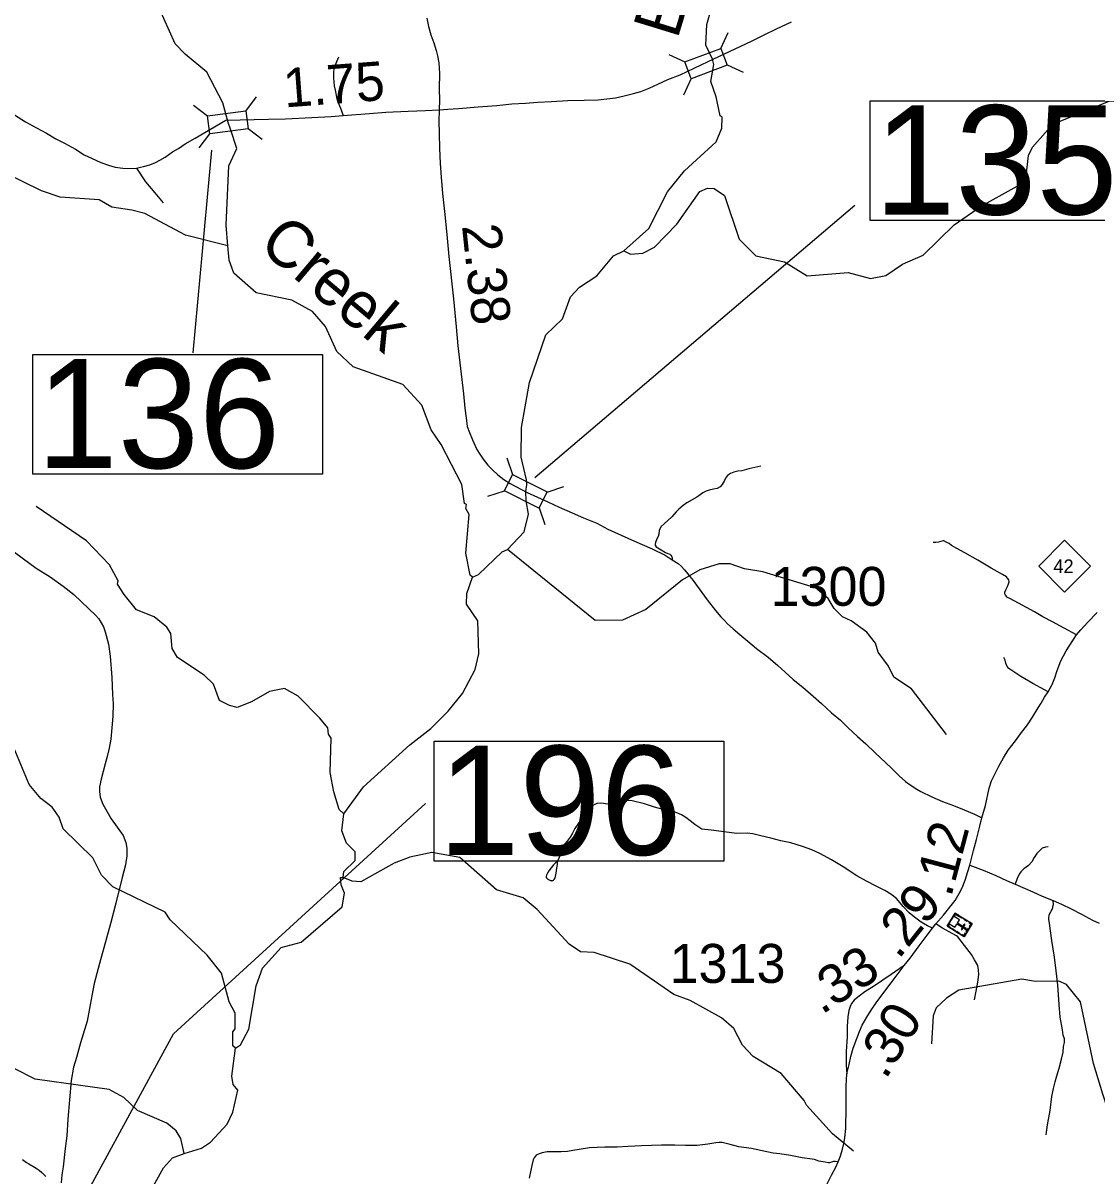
# Model space of a CAD drawing. Extents: x 2290615 to 2522933, y 819489 to 1012715.
# Drawn here: x 2331750 to 2345527, y 928394 to 943186 of the extents above; entities that cross this region are included whole.
import ezdxf

# ---------------------------------------------------------------- set-up
doc = ezdxf.new("R2010")
doc.units = 0
for name, color, linetype in [('Exist Cultural Church with Cemetery CELL', 7, 'Continuous'), ('Exist Hydrographic Creek Single Shore', 7, 'Continuous'), ('Exist Hydrographic Creek Single Shore Label', 7, 'Continuous'), ('Exist Hydrographic Misc Water Feature', 7, 'Continuous'), ('Exist Road Non-System Type 51', 7, 'Continuous'), ('Exist Road Primary NC Attributed', 7, 'Continuous'), ('Exist Road Primary NC Mileage Hundredths English Label', 7, 'Continuous'), ('Exist Road Primary NC Shield CELL', 7, 'Continuous'), ('Exist Road Primary NC Shield Number Label', 7, 'Continuous'), ('Exist Road Secondary Mileage Hundredths English Label', 7, 'Continuous'), ('Exist Road Secondary Structure Standard Bridge CELL', 7, 'Continuous'), ('Exist Road Secondary Structure Standard Bridge Number Label', 7, 'Continuous'), ('Exist Road Secondary Type 41 Attributed', 7, 'Continuous'), ('Exist Road Secondary Type 51 Attributed', 7, 'Continuous'), ('Exist Road Secondary Type 51 Number Label', 7, 'Continuous')]:
    doc.layers.add(name, color=color, linetype=linetype)

msp = doc.modelspace()

# ---------------------------------------------------------------- linework, layer by layer
at = {"layer": 'Exist Cultural Church with Cemetery CELL'}
for points in [[(2343927, 931632), (2343822, 931462), (2343606, 931597), (2343710, 931766)], [(2343693, 931738), (2343703, 931732), (2343714, 931750), (2343749, 931729), (2343755, 931739), (2343710, 931766)], [(2343623, 931625), (2343633, 931619), (2343621, 931600), (2343655, 931579), (2343650, 931569), (2343606, 931597)], [(2343688, 931729), (2343629, 931634), (2343706, 931586), (2343732, 931629), (2343802, 931586), (2343784, 931558), (2343794, 931553), (2343811, 931581), (2343847, 931558), (2343853, 931568), (2343817, 931590), (2343835, 931619), (2343825, 931624), (2343808, 931596), (2343738, 931639), (2343765, 931682)], [(2343770, 931729), (2343807, 931706), (2343801, 931697), (2343764, 931719)], [(2343827, 931694), (2343864, 931671), (2343858, 931661), (2343821, 931684)], [(2343890, 931655), (2343884, 931645), (2343911, 931628), (2343890, 931593), (2343899, 931588), (2343927, 931632)], [(2343673, 931568), (2343710, 931545), (2343704, 931536), (2343667, 931559)], [(2343729, 931533), (2343766, 931511), (2343760, 931501), (2343723, 931524)], [(2343785, 931485), (2343791, 931495), (2343818, 931478), (2343840, 931512), (2343849, 931507), (2343822, 931462)], [(2343888, 931569), (2343860, 931525), (2343851, 931531), (2343878, 931575)]]:
    msp.add_lwpolyline(points, close=True, dxfattribs=at)
at = {"layer": 'Exist Hydrographic Creek Single Shore'}
for points in [[(2339458, 940266), (2339780, 940551), (2340016, 941021), (2340237, 941289), (2340641, 941663), (2340714, 941837), (2340721, 941979), (2340695, 941997), (2340643, 942238), (2340573, 942435), (2340610, 942656), (2340595, 942721), (2340510, 942902), (2340523, 943169), (2340787, 944105), (2340842, 944357), (2340819, 944904), (2340792, 945031), (2340750, 945105), (2340758, 945138), (2340732, 945163), (2340653, 945554), (2340650, 945787)], [(2334376, 940329), (2334356, 940594), (2334388, 941354), (2334494, 941578), (2334412, 941823), (2334381, 941910), (2334312, 942162), (2334107, 942557), (2333830, 942788), (2333703, 942921), (2333481, 943408)], [(2337517, 936076), (2337484, 936101), (2337431, 936385), (2337475, 936882), (2337432, 936959), (2337440, 937009), (2337415, 937024), (2337378, 937265), (2337114, 937780), (2336987, 937968), (2336866, 938285), (2336621, 938547), (2335986, 938774), (2335775, 938972), (2335629, 939294), (2335461, 939484), (2335200, 939631), (2334741, 939724), (2334455, 939978), (2334394, 940146), (2334376, 940329)], [(2337963, 936433), (2338177, 936658), (2338233, 936884), (2338203, 937058), (2338200, 937174), (2338211, 937260), (2338208, 937324), (2338140, 937615), (2338144, 937999), (2338246, 938575), (2338455, 939187), (2338669, 939390), (2338774, 939673), (2338889, 939799), (2339112, 939943), (2339326, 940198), (2339458, 940266)], [(2337517, 936076), (2337592, 936109), (2337897, 936404), (2337963, 936433)], [(2335863, 933041), (2336117, 933386), (2336710, 933926), (2336983, 934137), (2337205, 934357), (2337386, 934584), (2337548, 934893), (2337596, 935095), (2337583, 935518), (2337438, 935732), (2337445, 935867), (2337517, 936076)], [(2335856, 932223), (2335863, 932299), (2336012, 932443), (2336010, 932551), (2335901, 932665), (2335840, 932823), (2335863, 933041)], [(2334475, 930033), (2334540, 930075), (2334646, 930276), (2334740, 930835), (2334820, 931062), (2335059, 931324), (2335316, 931394), (2335844, 931849), (2335875, 932024), (2335832, 932131), (2335823, 932222), (2335856, 932223)], [(2333816, 928683), (2334040, 928752), (2334156, 928828), (2334370, 929057), (2334443, 929214), (2334506, 929493), (2334447, 929566), (2334429, 929673), (2334475, 930033)], [(2332562, 927644), (2332603, 927701), (2332669, 927720), (2332828, 927687), (2333044, 927732), (2333250, 927951), (2333551, 928498), (2333667, 928625), (2333816, 928683)]]:
    msp.add_lwpolyline(points, dxfattribs=at)
at = {"layer": 'Exist Hydrographic Misc Water Feature'}
for points in [[(2339458, 940266), (2339542, 940223), (2339700, 940233), (2339849, 940311), (2340137, 940605), (2340432, 941025), (2340532, 941068), (2340615, 941062), (2340749, 940972), (2340939, 940415), (2341150, 940201), (2341518, 940124), (2341811, 939942), (2342336, 939984), (2342620, 939910), (2342820, 939948), (2343034, 940091), (2343299, 940210), (2343695, 940597), (2344042, 940835), (2344505, 941094), (2344620, 941220), (2344650, 941487), (2344699, 941594), (2344962, 941890), (2345758, 942215)], [(2334376, 940329), (2333833, 940465), (2333313, 940742), (2333146, 940787), (2332887, 940826), (2332727, 940918), (2332227, 940953), (2331985, 941032), (2331507, 941268)], [(2335863, 933041), (2335804, 933098), (2335735, 933321), (2335690, 933572), (2335701, 934013), (2335667, 934064), (2335658, 934145), (2335557, 934269), (2335278, 934550), (2335102, 934648), (2334911, 934610), (2334679, 934476), (2334497, 934406), (2334397, 934432), (2334271, 934495), (2334193, 934702), (2334075, 934819), (2333731, 935048), (2333663, 935163), (2333644, 935356), (2333593, 935436), (2333433, 935567), (2333207, 935656), (2333046, 935856), (2332962, 935988), (2332969, 936031), (2332859, 936236), (2332563, 936542), (2331917, 936982)], [(2343598, 934058), (2343150, 934644), (2342923, 934792), (2342855, 934933), (2342719, 935115), (2342685, 935228), (2342574, 935372), (2342373, 935518), (2342264, 935566), (2342154, 935673), (2342078, 935804), (2341918, 935939), (2341240, 936147), (2341007, 936184), (2340823, 936248), (2340681, 936246), (2340432, 936170), (2340209, 936042), (2339739, 935662), (2339440, 935525), (2339090, 935521), (2337963, 936433)], [(2334475, 930033), (2334441, 930065), (2334439, 930242), (2334471, 930282), (2334469, 930483), (2334392, 930630), (2334296, 930997), (2334110, 931229), (2333638, 931679), (2333571, 931778), (2332900, 932105), (2332757, 932254), (2332646, 932476), (2332266, 932847), (2332215, 932996), (2332121, 933127), (2331978, 933236), (2331826, 933417), (2331594, 933982)], [(2342406, 928711), (2342135, 928933), (2341799, 929303), (2341773, 929361), (2341476, 929710), (2341116, 929928), (2340980, 930071), (2340869, 930286), (2340711, 930424), (2340307, 930644), (2340098, 930724), (2339535, 931111), (2339075, 931263), (2338900, 931269), (2338757, 931368), (2338344, 931814), (2338167, 931961), (2337824, 932065), (2337352, 932482), (2336993, 932546), (2336711, 932485), (2336512, 932408), (2336082, 932167), (2335973, 932176), (2335856, 932223)], [(2346076, 928291), (2346082, 928471), (2345803, 928828), (2345603, 929443), (2345483, 929839), (2345315, 930629), (2345138, 930852), (2345037, 930894), (2344737, 930888), (2344562, 930920), (2343755, 930779), (2343597, 930677), (2343466, 930550), (2343425, 930450), (2343405, 930091)], [(2333816, 928683), (2333772, 928875), (2333712, 928974), (2333595, 929071), (2333218, 929233), (2333041, 929400), (2332856, 929504), (2331905, 929635), (2331637, 929772)]]:
    msp.add_lwpolyline(points, dxfattribs=at)
at = {"layer": 'Exist Road Non-System Type 51'}
for points in [[(2335798, 942749), (2335773, 942688), (2335743, 942616), (2335734, 942563), (2335731, 942483), (2335743, 942382), (2335756, 942325), (2335776, 942214), (2335788, 942174), (2335823, 942094), (2335858, 942000)], [(2333204, 941326), (2333319, 941148), (2333439, 941007), (2333546, 940881)], [(2341216, 937500), (2341138, 937485), (2341063, 937465), (2340970, 937441), (2340918, 937435), (2340867, 937425), (2340827, 937408), (2340789, 937381), (2340762, 937348), (2340744, 937307), (2340719, 937265), (2340692, 937235), (2340656, 937213), (2340607, 937204), (2340553, 937194), (2340514, 937182), (2340473, 937159), (2340420, 937122), (2340396, 937104), (2340265, 937029), (2340217, 936996), (2340165, 936951), (2340127, 936914), (2340072, 936853), (2339974, 936761), (2339938, 936726), (2339918, 936698), (2339911, 936676), (2339908, 936630), (2339899, 936597), (2339880, 936567), (2339863, 936522), (2339858, 936500), (2339858, 936487), (2339873, 936467), (2339935, 936426), (2339993, 936395), (2340021, 936380), (2340047, 936370), (2340062, 936359), (2340071, 936347), (2340079, 936327), (2340076, 936300)], [(2345265, 935337), (2345107, 935421), (2344957, 935502), (2344834, 935567), (2344725, 935633), (2344520, 935744), (2344409, 935801), (2344381, 935818), (2344354, 935846), (2344347, 935864), (2344347, 935883), (2344358, 935914), (2344379, 935956), (2344392, 935990), (2344400, 936017), (2344396, 936041), (2344381, 936063), (2344366, 936083), (2344316, 936113), (2344172, 936191), (2343998, 936297), (2343832, 936390), (2343731, 936445), (2343663, 936485), (2343630, 936507), (2343600, 936523), (2343563, 936541), (2343563, 936541), (2343554, 936541), (2343525, 936535), (2343494, 936528), (2343461, 936523), (2343428, 936521)], [(2344901, 934607), (2344706, 934713), (2344551, 934804), (2344396, 934903), (2344375, 934932), (2344358, 934974), (2344349, 935010), (2344332, 935048)], [(2343418, 931573), (2343355, 931604), (2343272, 931652), (2343188, 931714), (2343118, 931770), (2343045, 931847), (2342954, 931953), (2342882, 932008), (2342805, 932057), (2342696, 932114), (2342569, 932177), (2342448, 932246), (2342272, 932362), (2342122, 932449), (2341970, 932532), (2341871, 932578), (2341748, 932623), (2341600, 932667), (2341472, 932693), (2341345, 932729), (2341214, 932757), (2341114, 932782), (2341038, 932791), (2340904, 932789), (2340746, 932811), (2340577, 932832), (2340460, 932845), (2340419, 932869), (2340367, 932905), (2340310, 932952), (2340252, 932993), (2340197, 933027), (2340117, 933060), (2340007, 933084), (2339852, 933124), (2339724, 933167), (2339565, 933207), (2339449, 933214), (2339399, 933203), (2339340, 933182), (2339298, 933168), (2339250, 933165), (2339198, 933175), (2339152, 933178), (2339110, 933172), (2339050, 933141), (2339019, 933114), (2338961, 933040), (2338922, 932987), (2338829, 932851), (2338797, 932794), (2338768, 932743), (2338730, 932690), (2338683, 932633), (2338668, 932614), (2338651, 932592), (2338647, 932573), (2338639, 932537), (2338634, 932516), (2338630, 932491), (2338622, 932468), (2338607, 932438)], [(2344903, 932615), (2344867, 932611), (2344823, 932598), (2344756, 932530), (2344723, 932481), (2344690, 932425), (2344648, 932378), (2344589, 932336), (2344551, 932297), (2344529, 932267), (2344504, 932209), (2344480, 932139)], [(2338607, 932438), (2338556, 932385), (2338526, 932347), (2338495, 932307), (2338478, 932279), (2338468, 932263), (2338464, 932254), (2338460, 932235), (2338462, 932222), (2338472, 932209), (2338484, 932200), (2338498, 932195), (2338515, 932187), (2338526, 932183), (2338532, 932182), (2338540, 932183), (2338546, 932185), (2338554, 932190), (2338564, 932197), (2338571, 932211), (2338581, 932236), (2338589, 932279), (2338598, 932345), (2338605, 932390), (2338608, 932417), (2338607, 932438)], [(2344876, 928920), (2344895, 929049), (2344928, 929236), (2344950, 929412), (2344968, 929518), (2344990, 929603), (2345012, 929680), (2345041, 929775), (2345074, 929893), (2345093, 929984), (2345100, 930054), (2345111, 930105), (2345111, 930153), (2345096, 930201), (2345085, 930270), (2345056, 930432), (2345041, 930593), (2345027, 930843), (2345005, 931026), (2344983, 931202), (2344950, 931415), (2344931, 931540), (2344917, 931639), (2344909, 931686), (2344909, 931708), (2344913, 931741), (2344924, 931763), (2344942, 931793), (2344953, 931811), (2344962, 931838), (2344966, 931869), (2344968, 931873), (2344964, 931930)], [(2343955, 930653), (2343976, 930764), (2343997, 930882), (2344012, 930977), (2344007, 931039), (2343997, 931093), (2343955, 931166), (2343919, 931234), (2343828, 931351), (2343742, 931462), (2343724, 931475), (2343668, 931505), (2343547, 931572), (2343461, 931628)], [(2342208, 928574), (2342168, 928579), (2342146, 928579), (2342095, 928563), (2342077, 928562), (2342040, 928571), (2341959, 928585), (2341902, 928605), (2341746, 928628), (2341594, 928658), (2341458, 928678), (2341372, 928688), (2341232, 928715), (2341095, 928745), (2340934, 928769), (2340820, 928797), (2340720, 928824), (2340682, 928824), (2340636, 928821), (2340534, 928802), (2340398, 928786), (2340250, 928784), (2340112, 928789), (2339940, 928787), (2339685, 928780), (2339513, 928773), (2339371, 928764), (2339215, 928762), (2339019, 928754), (2338883, 928732), (2338803, 928719), (2338734, 928706), (2338654, 928705), (2338568, 928704), (2338472, 928705), (2338408, 928692), (2338370, 928680), (2338334, 928661), (2338309, 928627), (2338295, 928601), (2338278, 928527), (2338265, 928467), (2338244, 928366)], [(2331742, 928604), (2331792, 928568), (2331824, 928548), (2331873, 928518), (2331916, 928492), (2331955, 928467), (2331992, 928438), (2332044, 928386)]]:
    msp.add_lwpolyline(points, dxfattribs=at)
at = {"layer": 'Exist Road Primary NC Attributed'}
for points in [[(2344049, 932987), (2344097, 933148), (2344146, 933370), (2344176, 933463), (2344269, 933651), (2344328, 933758), (2344390, 933859), (2344483, 933976), (2344548, 934067), (2344636, 934182), (2344701, 934279), (2344774, 934400), (2344811, 934459), (2344854, 934539), (2344901, 934607), (2344952, 934699), (2344985, 934786), (2345018, 934880), (2345066, 935005), (2345133, 935130), (2345178, 935206), (2345217, 935266), (2345265, 935337), (2345322, 935402), (2345410, 935501), (2345529, 935622)], [(2343898, 932383), (2343944, 932568), (2343982, 932712), (2344024, 932883), (2344049, 932987)], [(2343052, 931094), (2343129, 931188), (2343245, 931348), (2343347, 931483), (2343418, 931573), (2343461, 931628), (2343558, 931741), (2343639, 931842), (2343708, 931929), (2343759, 932018), (2343800, 932090), (2343837, 932191), (2343871, 932299), (2343898, 932383)], [(2342318, 929706), (2342349, 929825), (2342370, 929926), (2342399, 930034), (2342445, 930156), (2342480, 930247), (2342517, 930329), (2342574, 930432), (2342629, 930521), (2342694, 930617), (2342780, 930730), (2342887, 930872), (2343052, 931094)], [(2342039, 928242), (2342123, 928403), (2342177, 928508), (2342208, 928574), (2342234, 928640), (2342257, 928719), (2342280, 928811), (2342294, 928885), (2342304, 929005), (2342307, 929095), (2342311, 929187), (2342311, 929345), (2342309, 929552), (2342318, 929706)]]:
    msp.add_lwpolyline(points, dxfattribs=at)
at = {"layer": 'Exist Road Primary NC Shield CELL'}
msp.add_lwpolyline([(2344780, 936219), (2345113, 936552), (2345446, 936219), (2345113, 935886)], close=True, dxfattribs=at)
at = {"layer": 'Exist Road Secondary Structure Standard Bridge CELL'}
for p, q in [((2340704, 942861), (2340797, 943067)), ((2340033, 942782), (2340239, 942688)), ((2340783, 942649), (2340989, 942555)), ((2340226, 942265), (2340320, 942471)), ((2333937, 942132), (2334117, 941994)), ((2334609, 942058), (2334746, 942238)), ((2334638, 941834), (2334818, 941696)), ((2334010, 941585), (2334147, 941765)), ((2337958, 937607), (2338029, 937393)), ((2338472, 937169), (2338687, 937241)), ((2337711, 937114), (2337926, 937186)), ((2338371, 936967), (2338442, 936752))]:
    msp.add_line(p, q, dxfattribs=at)
for points in [[(2340239, 942688), (2340703, 942862), (2340784, 942645), (2340320, 942471)], [(2334117, 941994), (2334608, 942059), (2334639, 941830), (2334147, 941765)], [(2338029, 937393), (2338473, 937170), (2338369, 936963), (2337926, 937186)]]:
    msp.add_lwpolyline(points, close=True, dxfattribs=at)
at = {"layer": 'Exist Road Secondary Structure Standard Bridge Number Label'}
for p, q in [((2334166, 941557), (2333929, 938954)), ((2338314, 937355), (2342422, 940851))]:
    msp.add_line(p, q, dxfattribs=at)
for points in [[(2342619, 942188), (2346335, 942188), (2346335, 940651), (2342619, 940651)], [(2331874, 938934), (2335590, 938934), (2335590, 937397), (2331874, 937397)], [(2337026, 933971), (2340742, 933971), (2340742, 932435), (2337026, 932435)]]:
    msp.add_lwpolyline(points, close=True, dxfattribs=at)
msp.add_lwpolyline([(2332142, 927385), (2333681, 930217), (2336913, 933172)], dxfattribs=at)
at = {"layer": 'Exist Road Secondary Type 41 Attributed'}
msp.add_lwpolyline([(2331558, 936456), (2331919, 936194), (2332096, 936080), (2332263, 935962), (2332403, 935853), (2332684, 935587), (2332721, 935542), (2332782, 935439), (2332804, 935374), (2332847, 935219), (2332866, 935064), (2332888, 934790), (2332898, 934572), (2332907, 934452), (2332900, 934292), (2332888, 934142), (2332874, 933998), (2332854, 933881), (2332829, 933778), (2332803, 933682), (2332750, 933485), (2332730, 933386), (2332730, 933326), (2332739, 933255), (2332775, 933163), (2332824, 933073), (2332881, 932976), (2333033, 932764), (2333067, 932674), (2333081, 932601), (2333083, 932582), (2333081, 932500), (2333062, 932386), (2333021, 932223), (2332941, 931893), (2332877, 931645), (2332730, 931122), (2332664, 930863), (2332632, 930707), (2332573, 930382), (2332487, 930104), (2332434, 929916), (2332396, 929791), (2332368, 929617), (2332324, 929121), (2332313, 928909), (2332290, 928746), (2332265, 928510), (2332249, 928409), (2332237, 928306)], dxfattribs=at)
at = {"layer": 'Exist Road Secondary Type 51 Attributed'}
for points in [[(2336929, 943249), (2336950, 943143), (2336982, 943037), (2337019, 942932), (2337048, 942834), (2337067, 942766), (2337082, 942677), (2337091, 942539), (2337088, 942345), (2337092, 942199), (2337087, 942075)], [(2340538, 942694), (2341096, 942955), (2341259, 943035), (2341414, 943113), (2341607, 943201)], [(2337087, 942075), (2337199, 942080), (2337337, 942090), (2337588, 942111), (2337828, 942130), (2338022, 942148), (2338194, 942160), (2338352, 942172), (2338529, 942182), (2338741, 942191), (2338950, 942199), (2339129, 942201), (2339349, 942227), (2339463, 942252), (2339580, 942284), (2339676, 942310), (2339781, 942350), (2339894, 942402), (2340024, 942462), (2340181, 942524), (2340538, 942694)], [(2331641, 942009), (2331782, 941919), (2331921, 941841), (2332050, 941772), (2332171, 941702), (2332280, 941644), (2332422, 941567), (2332535, 941496), (2332627, 941452), (2332747, 941397), (2332848, 941363), (2332933, 941339), (2333029, 941326), (2333132, 941321), (2333204, 941326), (2333258, 941339), (2333295, 941348), (2333378, 941369), (2333448, 941397), (2333504, 941429), (2333572, 941467), (2333665, 941532), (2333745, 941579), (2333830, 941637), (2333956, 941710), (2334353, 941939)], [(2334353, 941939), (2334900, 941955), (2335118, 941958), (2335455, 941973), (2335702, 941988), (2335858, 942000), (2336193, 942028), (2336406, 942041), (2336690, 942054), (2336911, 942064), (2337087, 942075)], [(2337087, 942075), (2337085, 941929), (2337089, 941771), (2337091, 941581), (2337103, 941385), (2337116, 941207), (2337132, 940998), (2337159, 940732), (2337191, 940426), (2337214, 940193), (2337270, 939649), (2337308, 939288), (2337328, 939047), (2337363, 938753), (2337399, 938427), (2337416, 938244), (2337433, 938121), (2337449, 938008), (2337476, 937933), (2337518, 937839), (2337573, 937716), (2337608, 937654), (2337651, 937591), (2337714, 937514), (2337771, 937452), (2337839, 937391), (2337916, 937332), (2337997, 937279), (2338217, 937163)], [(2338217, 937163), (2338481, 937043), (2338626, 936975), (2338795, 936903), (2338938, 936837), (2339109, 936769), (2339251, 936694), (2339422, 936614), (2339593, 936539), (2339821, 936440), (2339988, 936359), (2340076, 936300), (2340155, 936251), (2340195, 936218), (2340235, 936169), (2340275, 936124), (2340303, 936086), (2340345, 936034), (2340390, 935974), (2340422, 935927), (2340526, 935788), (2340632, 935650), (2340701, 935570), (2340747, 935519), (2340788, 935477), (2340858, 935416), (2340947, 935341), (2341050, 935254), (2341161, 935160), (2341310, 935051), (2341432, 934945), (2341529, 934856), (2341630, 934765), (2341752, 934666), (2341887, 934550), (2341994, 934454), (2342123, 934335), (2342236, 934241), (2342335, 934144), (2342455, 934034), (2342563, 933940), (2342682, 933821), (2342887, 933631), (2342991, 933528), (2343072, 933455), (2343144, 933404), (2343217, 933356), (2343267, 933328), (2343407, 933258), (2343546, 933200), (2343687, 933147), (2343822, 933090), (2343956, 933034), (2344049, 932987)], [(2343898, 932383), (2344066, 932319), (2344229, 932248), (2344368, 932185), (2344480, 932139), (2344606, 932083), (2344706, 932039), (2344825, 931985), (2344964, 931930), (2345071, 931883), (2345197, 931820), (2345329, 931754), (2345472, 931678), (2345555, 931639)], [(2343052, 931094), (2342886, 930977), (2342673, 930835), (2342550, 930756), (2342459, 930686), (2342413, 930650), (2342394, 930629), (2342380, 930606), (2342363, 930569)], [(2342363, 930569), (2342344, 930515), (2342332, 930436), (2342321, 930313), (2342321, 930181), (2342310, 929991), (2342308, 929896), (2342308, 929816), (2342318, 929706)]]:
    msp.add_lwpolyline(points, dxfattribs=at)

# ---------------------------------------------------------------- texts
at = {"layer": 'Exist Hydrographic Creek Single Shore Label'}
for s, rotation, p in [('Bear', 72.9425, (2340143, 942968)), ('Creek', 319.8247, (2334750, 940312))]:
    msp.add_text(s, height=600, rotation=rotation, dxfattribs=at).set_placement(p)
at = {"layer": 'Exist Road Primary NC Mileage Hundredths English Label'}
for s, rotation, p in [('.12', 75.1543, (2343655, 931958)), ('.29', 51.3663, (2342982, 931162)), ('.30', 58.2046, (2342815, 929620))]:
    msp.add_text(s, height=500, rotation=rotation, dxfattribs=at).set_placement(p)
at = {"layer": 'Exist Road Primary NC Shield Number Label'}
msp.add_text('42', height=175, dxfattribs=at).set_placement((2344968, 936129))
at = {"layer": 'Exist Road Secondary Mileage Hundredths English Label'}
for s, rotation, p in [('1.75', 4.334, (2335107, 942103)), ('2.38', 276.0459, (2337380, 940588)), ('.33', 32.8303, (2341995, 930457))]:
    msp.add_text(s, height=500, rotation=rotation, dxfattribs=at).set_placement(p)
at = {"layer": 'Exist Road Secondary Structure Standard Bridge Number Label'}
for s, p in [('135', (2342669, 940730)), ('136', (2331924, 937476)), ('196', (2337076, 932514))]:
    msp.add_text(s, height=1400, dxfattribs=at).set_placement(p)
at = {"layer": 'Exist Road Secondary Type 51 Number Label'}
for s, p in [('1300', (2341340, 935709)), ('1313', (2340044, 930871))]:
    msp.add_text(s, height=500, rotation=360, dxfattribs=at).set_placement(p)

doc.saveas('drawing.dxf')
